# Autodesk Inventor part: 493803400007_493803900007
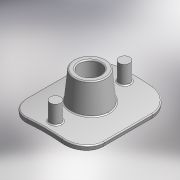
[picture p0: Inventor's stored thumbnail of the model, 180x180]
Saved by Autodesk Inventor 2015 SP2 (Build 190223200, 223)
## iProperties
Created: 2019-01
Part Number: 493803400007_493803900007
Material: PVC-Piping
Description: PLASSON SENSOR ADAPTOR 3/4''
Document SubType Name: Modeling
Designer: KIM
Mass: 107.737 g
Surface Area: 256.113 cm^2
Volume: 76.9548 cm^3
Density: 1.4 g/cm^3
Appearance: Smooth - White
Author: KIM
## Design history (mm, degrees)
derived "493803.ipt"
feature "Solid1::493803.ipt" dims "ScaleForDerivedMember" = 10
tag "TaggingFeature1"
body "Solid1"
other parameters: "d0" = 38 [user parameter], "d1" = 103 [user parameter], "d4" = 85 [user parameter], "d6" = 206 [user parameter], "d8" = 103 [user parameter], "d9" = 0 [user parameter], "d10" = 26.6 [user parameter], "d11" = 26.6 [user parameter], "d13" = 12.36 [user parameter], "d14" = 12.36 [user parameter], "d15" = 24.117 [user parameter], "d16" = 43.4106 [user parameter], "d17" = 36.1755 [user parameter], "d18" = 12.0585 [user parameter], "d20" = 12.0585 [user parameter], "d24" = 24.117 [user parameter], "d25" = 1.20585 [user parameter], "d27" = 0 [user parameter], "Rp" = 24.117 [user parameter], "H_" = 38 [user parameter], "B" = 85 [user parameter], "L" = 103 [user parameter]
